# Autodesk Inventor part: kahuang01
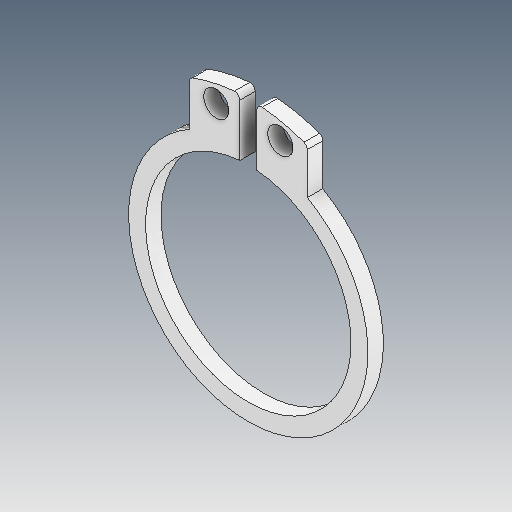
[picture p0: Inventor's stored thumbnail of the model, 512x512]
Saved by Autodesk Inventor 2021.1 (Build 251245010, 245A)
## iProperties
Created: 2021-05
Part Number: kahuang01
Material: Ogólny
Document SubType Name: Modeling
Designer: user
Density: 1 g/cm^3
Appearance: Domyślna
Author: user
Revision Number: ÈÎºÎ
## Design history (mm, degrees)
feature "ÊäÈë1"
node "Bryła1"
